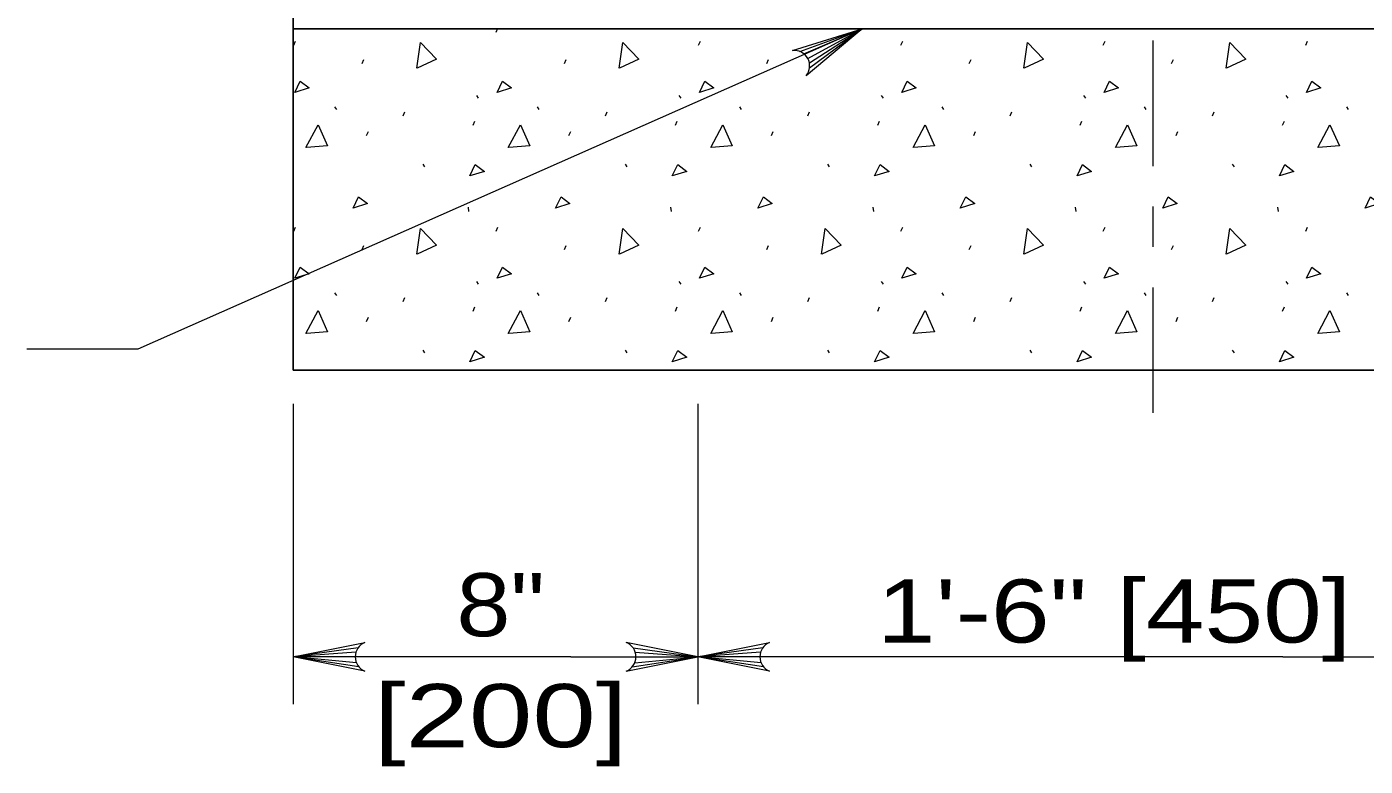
# Model space of a CAD drawing. Extents: x 1083.1 to 1117.1, y 719.4 to 763.4.
# Drawn here: x 1105.374 to 1108.681, y 727.814 to 729.641 of the extents above; entities that cross this region are included whole.
import ezdxf
from ezdxf.enums import TextEntityAlignment as Align

# ---------------------------------------------------------------- set-up
doc = ezdxf.new("R2010")
doc.units = 0
doc.header["$LTSCALE"] = 0.062
doc.linetypes.add('DOT_DASHED', pattern=[7.7, 5, -1.2, 0.3, -1.2])
doc.layers.add('1', color=7, linetype='Continuous', lineweight=13)

msp = doc.modelspace()

# ---------------------------------------------------------------- linework, layer by layer
at = {"layer": '1', "linetype": 'DOT_DASHED'}
msp.add_line((1108.1575, 728.68675), (1108.1575, 733.12358), dxfattribs=at)
at = {"layer": '1', "lineweight": 25}
for p, q in [((1106.03258, 728.79217), (1106.03258, 732.8195)), ((1110.28242, 728.79217), (1106.03258, 728.79217))]:
    msp.add_line(p, q, dxfattribs=at)
at = {"layer": '1'}
for p, q in [((1106.53408, 729.62758), (1106.5385, 729.63758)), ((1107.28408, 729.57992), (1107.4385, 729.6355)), ((1107.29442, 729.57375), (1107.4385, 729.6355)), ((1107.30383, 729.56242), (1107.4385, 729.6355)), ((1107.30775, 729.55167), (1107.4385, 729.6355)), ((1107.30825, 729.53933), (1107.4385, 729.6355)), ((1106.03408, 729.59525), (1106.0385, 729.60525)), ((1107.03408, 729.59525), (1107.0385, 729.60525)), ((1107.534, 729.59525), (1107.53842, 729.60525)), ((1108.034, 729.59525), (1108.03842, 729.60525)), ((1108.534, 729.59525), (1108.53842, 729.60525)), ((1106.20275, 729.54967), (1106.20725, 729.55967)), ((1106.70275, 729.54967), (1106.70725, 729.55967)), ((1107.20267, 729.54967), (1107.20717, 729.55967)), ((1107.70267, 729.54967), (1107.70717, 729.55967)), ((1108.20267, 729.54967), (1108.20717, 729.55967)), ((1106.48533, 729.47092), (1106.48983, 729.46425)), ((1106.98533, 729.47092), (1106.98983, 729.46425)), ((1107.48525, 729.47092), (1107.48975, 729.46425)), ((1107.98525, 729.47092), (1107.98975, 729.46425)), ((1108.48525, 729.47092), (1108.48975, 729.46425)), ((1106.13492, 729.44267), (1106.13933, 729.436)), ((1106.63492, 729.44267), (1106.63933, 729.436)), ((1107.13492, 729.44267), (1107.13933, 729.436)), ((1107.63483, 729.44267), (1107.63925, 729.436)), ((1108.13483, 729.44267), (1108.13925, 729.436)), ((1108.63483, 729.44267), (1108.63925, 729.436)), ((1106.30383, 729.42092), (1106.30825, 729.43092)), ((1106.477, 729.39775), (1106.48142, 729.40775)), ((1106.80383, 729.42092), (1106.80825, 729.43092)), ((1106.977, 729.39775), (1106.98142, 729.40775)), ((1107.30375, 729.42092), (1107.30817, 729.43092)), ((1107.47692, 729.39775), (1107.48133, 729.40775)), ((1107.80375, 729.42092), (1107.80817, 729.43092)), ((1107.97692, 729.39775), (1107.98133, 729.40775)), ((1108.30375, 729.42092), (1108.30817, 729.43092)), ((1108.47692, 729.39775), (1108.48133, 729.40775)), ((1106.21392, 729.37225), (1106.21833, 729.38225)), ((1106.71392, 729.37225), (1106.71833, 729.38225)), ((1107.21383, 729.37225), (1107.21825, 729.38225)), ((1107.71383, 729.37225), (1107.71825, 729.38225)), ((1108.21383, 729.37225), (1108.21825, 729.38225)), ((1106.35267, 729.30117), (1106.35708, 729.2945)), ((1106.85267, 729.30117), (1106.85708, 729.2945)), ((1107.35258, 729.30117), (1107.357, 729.2945)), ((1107.85258, 729.30117), (1107.857, 729.2945)), ((1108.35258, 729.30117), (1108.357, 729.2945)), ((1106.46483, 729.19475), (1106.466, 729.18475)), ((1106.96483, 729.19475), (1106.966, 729.18475)), ((1107.46475, 729.19475), (1107.46592, 729.18475)), ((1107.96475, 729.19475), (1107.96592, 729.18475)), ((1108.46475, 729.19475), (1108.46592, 729.18475)), ((1106.03408, 729.13583), (1106.0385, 729.14583)), ((1106.53408, 729.13583), (1106.5385, 729.14583)), ((1107.03408, 729.13583), (1107.0385, 729.14583)), ((1107.534, 729.13583), (1107.53842, 729.14583)), ((1108.034, 729.13583), (1108.03842, 729.14583)), ((1108.534, 729.13583), (1108.53842, 729.14583)), ((1106.20275, 729.09025), (1106.20725, 729.10025)), ((1106.70275, 729.09025), (1106.70725, 729.10025)), ((1107.20267, 729.09025), (1107.20717, 729.10025)), ((1107.70267, 729.09025), (1107.70717, 729.10025)), ((1108.20267, 729.09025), (1108.20717, 729.10025)), ((1106.48533, 729.01158), (1106.48983, 729.00492)), ((1106.98533, 729.01158), (1106.98983, 729.00492)), ((1107.48525, 729.01158), (1107.48975, 729.00492)), ((1107.98525, 729.01158), (1107.98975, 729.00492)), ((1108.48525, 729.01158), (1108.48975, 729.00492)), ((1106.13492, 728.98333), (1106.13933, 728.97667)), ((1106.63492, 728.98333), (1106.63933, 728.97667)), ((1107.13492, 728.98333), (1107.13933, 728.97667)), ((1107.63483, 728.98333), (1107.63925, 728.97667)), ((1108.13483, 728.98333), (1108.13925, 728.97667)), ((1108.63483, 728.98333), (1108.63925, 728.97667)), ((1106.30383, 728.96158), (1106.30825, 728.97158)), ((1106.477, 728.93842), (1106.48142, 728.94842)), ((1106.80383, 728.96158), (1106.80825, 728.97158)), ((1106.977, 728.93842), (1106.98142, 728.94842)), ((1107.30375, 728.96158), (1107.30817, 728.97158)), ((1107.47692, 728.93842), (1107.48133, 728.94842)), ((1107.80375, 728.96158), (1107.80817, 728.97158)), ((1107.97692, 728.93842), (1107.98133, 728.94842)), ((1108.30375, 728.96158), (1108.30817, 728.97158)), ((1108.47692, 728.93842), (1108.48133, 728.94842)), ((1106.21392, 728.91292), (1106.21833, 728.92292)), ((1106.71392, 728.91292), (1106.71833, 728.92292)), ((1107.21383, 728.91292), (1107.21825, 728.92292)), ((1107.71383, 728.91292), (1107.71825, 728.92292)), ((1108.21383, 728.91292), (1108.21825, 728.92292)), ((1106.35267, 728.84183), (1106.35708, 728.83517)), ((1106.85267, 728.84183), (1106.85708, 728.83517)), ((1107.35258, 728.84183), (1107.357, 728.83517)), ((1107.85258, 728.84183), (1107.857, 728.83517)), ((1108.35258, 728.84183), (1108.357, 728.83517)), ((1106.03258, 728.70883), (1106.03258, 727.96692)), ((1107.03258, 728.70883), (1107.03258, 727.96692)), ((1106.19292, 728.10633), (1106.03258, 728.08383)), ((1106.1875, 728.09517), (1106.03258, 728.08383)), ((1106.71842, 728.08383), (1106.03258, 728.08383)), ((1106.18583, 728.08383), (1106.03258, 728.08383)), ((1106.18867, 728.0695), (1106.03258, 728.08383)), ((1106.19483, 728.05908), (1106.03258, 728.08383)), ((1106.71842, 728.08383), (1107.03258, 728.08383)), ((1106.87033, 728.05908), (1107.03258, 728.08383)), ((1106.87225, 728.10633), (1107.03258, 728.08383)), ((1106.8765, 728.0695), (1107.03258, 728.08383)), ((1106.87767, 728.09517), (1107.03258, 728.08383)), ((1106.87933, 728.08383), (1107.03258, 728.08383)), ((1107.19283, 728.10633), (1107.03258, 728.08383)), ((1107.18742, 728.09517), (1107.03258, 728.08383)), ((1108.47742, 728.08383), (1107.03258, 728.08383)), ((1107.18575, 728.08383), (1107.03258, 728.08383)), ((1107.18858, 728.0695), (1107.03258, 728.08383)), ((1107.19475, 728.05908), (1107.03258, 728.08383)), ((1108.47742, 728.08383), (1109.28242, 728.08383))]:
    msp.add_line(p, q, dxfattribs=at)
for points in [[(1107.4385, 729.6355), (1105.64875, 728.84383), (1105.37425, 728.84383)], [(1107.26592, 729.58217), (1107.4385, 729.6355), (1107.29975, 729.51992)], [(1106.33783, 729.53825), (1106.34667, 729.60167), (1106.38642, 729.56058), (1106.33883, 729.53858)], [(1106.83783, 729.53825), (1106.84667, 729.60167), (1106.88642, 729.56058), (1106.83883, 729.53858)], [(1107.83775, 729.53825), (1107.84658, 729.60167), (1107.88633, 729.56058), (1107.83875, 729.53858)], [(1108.33775, 729.53825), (1108.34658, 729.60167), (1108.38633, 729.56058), (1108.33875, 729.53858)], [(1106.064, 729.34225), (1106.094, 729.39883), (1106.11733, 729.34675), (1106.06517, 729.34225)], [(1106.564, 729.34225), (1106.594, 729.39883), (1106.61733, 729.34675), (1106.56517, 729.34225)], [(1107.064, 729.34225), (1107.094, 729.39883), (1107.11725, 729.34675), (1107.06517, 729.34225)], [(1107.56392, 729.34225), (1107.59392, 729.39883), (1107.61725, 729.34675), (1107.56508, 729.34225)], [(1108.06392, 729.34225), (1108.09392, 729.39883), (1108.11725, 729.34675), (1108.06508, 729.34225)], [(1108.56392, 729.34225), (1108.59392, 729.39883), (1108.61725, 729.34675), (1108.56508, 729.34225)], [(1106.33783, 729.07883), (1106.34667, 729.14225), (1106.38642, 729.10117), (1106.33883, 729.07917)], [(1106.83783, 729.07883), (1106.84667, 729.14225), (1106.88642, 729.10117), (1106.83883, 729.07917)], [(1107.33775, 729.07883), (1107.34658, 729.14225), (1107.38633, 729.10117), (1107.33875, 729.07917)], [(1107.83775, 729.07883), (1107.84658, 729.14225), (1107.88633, 729.10117), (1107.83875, 729.07917)], [(1108.33775, 729.07883), (1108.34658, 729.14225), (1108.38633, 729.10117), (1108.33875, 729.07917)], [(1106.064, 728.88292), (1106.094, 728.9395), (1106.11733, 728.88742), (1106.06517, 728.88292)], [(1106.564, 728.88292), (1106.594, 728.9395), (1106.61733, 728.88742), (1106.56517, 728.88292)], [(1107.064, 728.88292), (1107.094, 728.9395), (1107.11725, 728.88742), (1107.06517, 728.88292)], [(1107.56392, 728.88292), (1107.59392, 728.9395), (1107.61725, 728.88742), (1107.56508, 728.88292)], [(1108.06392, 728.88292), (1108.09392, 728.9395), (1108.11725, 728.88742), (1108.06508, 728.88292)], [(1108.56392, 728.88292), (1108.59392, 728.9395), (1108.61725, 728.88742), (1108.56508, 728.88292)], [(1106.20967, 728.04842), (1106.03258, 728.08383), (1106.20967, 728.11925)], [(1106.8555, 728.04842), (1107.03258, 728.08383), (1106.8555, 728.11925)], [(1107.20958, 728.04842), (1107.03258, 728.08383), (1107.20958, 728.11925)]]:
    msp.add_lwpolyline(points, dxfattribs=at)
at = {"layer": '1', "lineweight": 25}
msp.add_lwpolyline([(1106.03258, 729.63575), (1109.65742, 729.63575), (1109.65742, 729.42475)], dxfattribs=at)
at = {"layer": '1'}
for points in [[(1106.03625, 729.47867), (1106.04958, 729.50642), (1106.07183, 729.48975)], [(1106.53625, 729.47867), (1106.54958, 729.50642), (1106.57183, 729.48975)], [(1107.03625, 729.47867), (1107.04958, 729.50642), (1107.07183, 729.48975)], [(1107.53617, 729.47867), (1107.5495, 729.50642), (1107.57175, 729.48975)], [(1108.03617, 729.47867), (1108.0495, 729.50642), (1108.07175, 729.48975)], [(1108.53617, 729.47867), (1108.5495, 729.50642), (1108.57175, 729.48975)], [(1106.46917, 729.27233), (1106.4825, 729.30008), (1106.50475, 729.28342)], [(1106.96917, 729.27233), (1106.9825, 729.30008), (1107.00475, 729.28342)], [(1107.46908, 729.27233), (1107.48242, 729.30008), (1107.50467, 729.28342)], [(1107.96908, 729.27233), (1107.98242, 729.30008), (1108.00467, 729.28342)], [(1108.46908, 729.27233), (1108.48242, 729.30008), (1108.50467, 729.28342)], [(1106.18083, 729.193), (1106.19417, 729.22075), (1106.21633, 729.20408)], [(1106.68083, 729.193), (1106.69417, 729.22075), (1106.71633, 729.20408)], [(1107.18075, 729.193), (1107.19408, 729.22075), (1107.21625, 729.20408)], [(1107.68075, 729.193), (1107.69408, 729.22075), (1107.71625, 729.20408)], [(1108.18075, 729.193), (1108.19408, 729.22075), (1108.21625, 729.20408)], [(1108.68075, 729.193), (1108.69408, 729.22075), (1108.71625, 729.20408)], [(1106.03625, 729.01933), (1106.04958, 729.04708), (1106.07183, 729.03042)], [(1106.53625, 729.01933), (1106.54958, 729.04708), (1106.57183, 729.03042)], [(1107.03625, 729.01933), (1107.04958, 729.04708), (1107.07183, 729.03042)], [(1107.53617, 729.01933), (1107.5495, 729.04708), (1107.57175, 729.03042)], [(1108.03617, 729.01933), (1108.0495, 729.04708), (1108.07175, 729.03042)], [(1108.53617, 729.01933), (1108.5495, 729.04708), (1108.57175, 729.03042)], [(1106.46917, 728.813), (1106.4825, 728.84075), (1106.50475, 728.82408)], [(1106.96917, 728.813), (1106.9825, 728.84075), (1107.00475, 728.82408)], [(1107.46908, 728.813), (1107.48242, 728.84075), (1107.50467, 728.82408)], [(1107.96908, 728.813), (1107.98242, 728.84075), (1108.00467, 728.82408)], [(1108.46908, 728.813), (1108.48242, 728.84075), (1108.50467, 728.82408)]]:
    msp.add_lwpolyline(points, close=True, dxfattribs=at)
for centre, start, end in [((1107.27029, 729.54421), 320.56627, 96.3924), ((1106.22397, 728.0839), 112.08782, 247.91395), ((1106.84117, 728.0839), 292.08605, 67.91218), ((1107.22392, 728.0839), 112.08782, 247.91395)]:
    msp.add_arc(centre, 0.03822, start, end, dxfattribs=at)

# ---------------------------------------------------------------- texts
for s, width, p in [('8"', 1.15, (1106.54508, 728.13475)), ('[200]', 1.35, (1106.54508, 727.86067))]:
    msp.add_text(s, height=0.156, dxfattribs=dict(at, width=width)).set_placement(p, align=Align.CENTER)
at = {"layer": '1', "width": 1.25}
msp.add_text('1\'-6" [450]', height=0.156, dxfattribs=at).set_placement((1107.47475, 728.11925))

doc.saveas('drawing.dxf')
